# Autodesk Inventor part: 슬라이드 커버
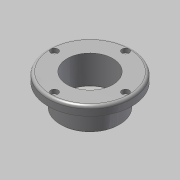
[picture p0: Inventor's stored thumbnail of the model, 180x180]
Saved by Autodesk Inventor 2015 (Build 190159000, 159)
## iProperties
Created: 2015-10
Part Number: 슬라이드 커버
Document SubType Name: Modeling
Designer: mdu
Density: 7.86 g/cm^3
Material: 강철, 연강
Mass: 598.523 g
Surface Area: 229.996 cm^2
Volume: 76.148 cm^3
Appearance: 강철
Author: mdu
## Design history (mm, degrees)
sketch "스케치1"
  geometry: C1 r 46 at (0, -39.25) reference; C2 r 32.5 at (0, -39.25) reference; 1 further point
  node "참조1"
  node "참조2"
extrude "돌출1" new body sketch "스케치1" distance "d0" = 10; taper "d1" = 0 deg
extrude "돌출2" join sketch "스케치1" distance "d2" = 25; taper "d3" = 0 deg
hole "구멍1" diameter "d6" = 50; stored, may be unused: countersink angle "d10" = 90 deg, drill point angle "d12" = 118 deg; dims "d4" = 10, "d5" = 10, "d7" = 6, "d8" = 4, "d9" = 2, "d11" = 8
sketch "스케치2"
  geometry: C1 r 46 at (0, 0) reference; C2 r 1.621 at (0, 39) reference; C3 r 1.621 at (39, 0) reference; C4 r 1.621 at (0, -39) reference; C5 r 1.621 at (-39, 0) reference; C6 r 33.5 at (0, 0) reference; 1 further point
hole "구멍2" sketch "스케치2" at (0, 39) diameter "d13" = 4.5; stored, may be unused: countersink angle "d17" = 90 deg, drill point angle "d19" = 118 deg; dims "d14" = 6, "d15" = 8, "d16" = 4.4, "d18" = 8
fillet "모깎기1" dims "d23" = 3
chamfer "모따기1" distance "d24" = 1; stored, may be unused: second distance "d25" = 2, angle "d26" = 45 deg
sketch "스케치3"
  geometry: C1 r 25 at (0, 0); C2 r 30 at (0, 0); C3 r 26 at (0, 0) reference; 1 further point
  constraints: 2 centre point, 2 coincident
  dimensions: "d27" = 60 diameter of C2
extrude "돌출3" cut sketch "스케치3" distance "d28" = 3; taper "d29" = 0 deg
chamfer "모따기2" distance "d30" = 1; stored, may be unused: second distance "d31" = 2, angle "d32" = 45 deg
node "솔리드1"
pattern_circular "원형 패턴1" dims angle "d21" = 360 deg
node "참조3"
